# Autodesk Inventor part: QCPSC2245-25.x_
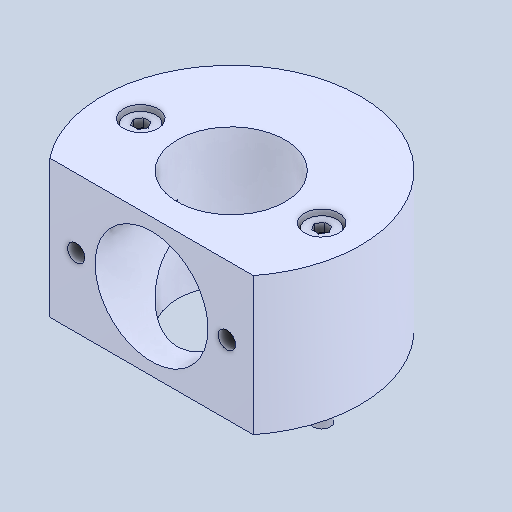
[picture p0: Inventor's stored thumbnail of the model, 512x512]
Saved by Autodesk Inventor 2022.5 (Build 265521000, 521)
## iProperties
Created: 2024-03
Part Number: QCPSC2245-25.x_
Material: 一般
Document SubType Name: Modeling
Designer: ImaoCorp
Density: 1 g/cm^3
Appearance: 既定
Author: ImaoCorp
Sending System: SOLIDWORKS 2022-2022290
MC: AMD64
MC_MODEL: Intel64 Family 6 Model 60 Stepping 3, GenuineIntel
OS: Windows_NT
FRU: Parasolid Version 33.1, build 260,  4-25-2022
FORMAT: text
GUISE: transmit
KEY: FILEQCPSC2245-25.x_t
DATE: Wed Mar  6 11:07:00 2024
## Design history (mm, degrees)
feature "Base1"
node "ソリッド1"
